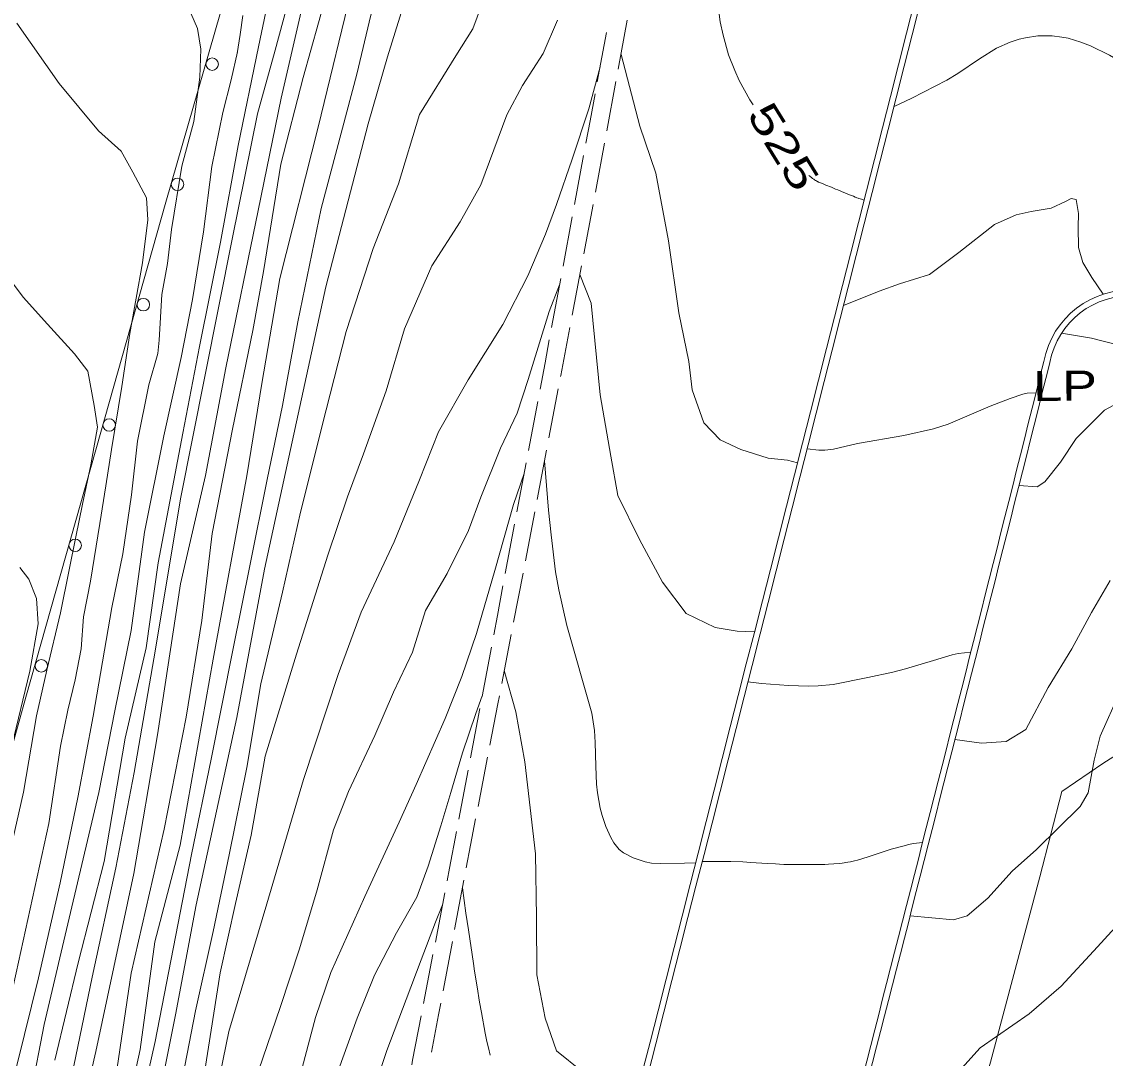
# Model space of a CAD drawing. Extents: x 2361284 to 2366480, y 6976556 to 6985346.
# Drawn here: x 2364861 to 2365034.3, y 6979380.2 to 6979546 of the extents above; entities that cross this region are included whole.
import ezdxf
from ezdxf.enums import TextEntityAlignment as Align

# ---------------------------------------------------------------- set-up
doc = ezdxf.new("R2010")
doc.units = 0
doc.header["$LTSCALE"] = 1.9
for name, color, linetype, lineweight in [('12', 7, 'Continuous', 13), ('13', 7, 'Continuous', 13), ('17', 7, 'Continuous', 13), ('3', 7, 'Continuous', 13), ('4', 7, 'Continuous', 13), ('6', 7, 'Continuous', 13)]:
    doc.layers.add(name, color=color, linetype=linetype, lineweight=lineweight)

msp = doc.modelspace()

# ---------------------------------------------------------------- linework, layer by layer
at = {"layer": '12'}
for points in [[(2364940.572, 6979651.492), (2364936.015, 6979640.658), (2364930.882, 6979627.349), (2364925.567, 6979614.168), (2364922.442, 6979603.148), (2364918.936, 6979587.914), (2364916.601, 6979576.84), (2364913.39, 6979563.3), (2364906.039, 6979537.048), (2364902.512, 6979523.173), (2364899.694, 6979506.046), (2364898.034, 6979496.58), (2364894.763, 6979480.837), (2364891.482, 6979464.115), (2364889.854, 6979450.23), (2364887.37, 6979434.784), (2364883.83, 6979416.87), (2364878.53, 6979393.849), (2364876.088, 6979377.264)], [(2364882.837, 6979492.905), (2364883.027, 6979495.067), (2364883.438, 6979502.371), (2364884.341, 6979507.3), (2364884.999, 6979512.745), (2364886.643, 6979522.873), (2364888.565, 6979530.031), (2364889.557, 6979537.121), (2364889.675, 6979541.602), (2364889.163, 6979544.897), (2364888.08, 6979547.307), (2364885.482, 6979551.383), (2364883.032, 6979555.57), (2364880.347, 6979560.225), (2364874.227, 6979570.787), (2364867.702, 6979580.676), (2364859.865, 6979594.061)], [(2364978.005, 6979532.672), (2364977.497, 6979533.487), (2364975.8, 6979536.569), (2364975.062, 6979538.169), (2364974.099, 6979540.655), (2364973.198, 6979543.811), (2364972.767, 6979545.938), (2364972.187, 6979550.237), (2364971.913, 6979555.136), (2364971.713, 6979561.675), (2364971.378, 6979564.921), (2364969.835, 6979573.586), (2364968.582, 6979579.184), (2364967.889, 6979581.263), (2364967.429, 6979582.294), (2364966.638, 6979583.721), (2364965.766, 6979584.888), (2364965.313, 6979585.334)], [(2364946.715, 6979546.205), (2364944.445, 6979540.863), (2364941.153, 6979535.761), (2364938.647, 6979531.077), (2364934.493, 6979519.867), (2364931.161, 6979513.945), (2364926.627, 6979506.932), (2364922.272, 6979496.88), (2364919.306, 6979486.94), (2364915.691, 6979476.877), (2364913.126, 6979470.022), (2364909.985, 6979460.681), (2364904.976, 6979444.852), (2364899.991, 6979428.514), (2364897.731, 6979415.882), (2364895.224, 6979404.968), (2364892.809, 6979393.874), (2364890.358, 6979378.279)], [(2365043.569, 6979537.876), (2365040.968, 6979538.031), (2365038.905, 6979538.365), (2365037.901, 6979538.691), (2365036.887, 6979539.274), (2365035.656, 6979540.226), (2365035.002, 6979540.644), (2365031.989, 6979542.103), (2365030.403, 6979542.72), (2365028.393, 6979543.31), (2365027.374, 6979543.516), (2365025.84, 6979543.707), (2365023.562, 6979543.705), (2365021.562, 6979543.414), (2365020.569, 6979543.173), (2365019.094, 6979542.694), (2365016.941, 6979541.712), (2365014.212, 6979540.026), (2365010.772, 6979537.666), (2365008.98, 6979536.597), (2365003.418, 6979533.731), (2365000.558, 6979532.436)], [(2364995.76, 6979517.45), (2364995.34, 6979517.581), (2364995.131, 6979517.648), (2364994.922, 6979517.717), (2364994.818, 6979517.753), (2364994.612, 6979517.827), (2364994.509, 6979517.866), (2364994.356, 6979517.926), (2364994.043, 6979518.053), (2364993.418, 6979518.309), (2364992.17, 6979518.824), (2364991.545, 6979519.08), (2364991.211, 6979519.216), (2364990.542, 6979519.487), (2364989.649, 6979519.847), (2364989.203, 6979520.027), (2364988.534, 6979520.301), (2364988.468, 6979520.329), (2364988.425, 6979520.349), (2364988.338, 6979520.39), (2364988.296, 6979520.411), (2364988.212, 6979520.455), (2364988.129, 6979520.502), (2364988.074, 6979520.534), (2364987.966, 6979520.601), (2364987.846, 6979520.679), (2364987.767, 6979520.733), (2364987.714, 6979520.77), (2364987.611, 6979520.845), (2364987.533, 6979520.902), (2364987.38, 6979521.019), (2364987.076, 6979521.257), (2364986.923, 6979521.376)], [(2364882.837, 6979492.905), (2364881.395, 6979487.89), (2364879.56, 6979478.913), (2364878.582, 6979470.324), (2364877.232, 6979460.909), (2364875.454, 6979452.323), (2364872.478, 6979434.953), (2364870.052, 6979421.929), (2364867.211, 6979408.282), (2364863.756, 6979393.098), (2364860.355, 6979379.514), (2364856.233, 6979363.845), (2364853.513, 6979348.078), (2364849.969, 6979332.753), (2364847.388, 6979320.178), (2364844.32, 6979304.148), (2364840.793, 6979286.013), (2364838.285, 6979270.979), (2364835.638, 6979258.063), (2364833.335, 6979244.72), (2364830.431, 6979230.282), (2364828.957, 6979222.287)], [(2365090.866, 6979426.919), (2365090.797, 6979426.888), (2365083.489, 6979425.51), (2365077.442, 6979424.101), (2365067.089, 6979423.363), (2365058.669, 6979422.293), (2365053.493, 6979419.673), (2365048.99, 6979416.8), (2365044.078, 6979409.723), (2365038.145, 6979403.617), (2365033.068, 6979398.048), (2365027.257, 6979391.763), (2365022.139, 6979387.334), (2365014.301, 6979381.889), (2365009.957, 6979377.046), (2365004.624, 6979368.746), (2365002.393, 6979364.705), (2364999.96, 6979360.762), (2364997.599, 6979357.698), (2364995.39, 6979356.567), (2364991.199, 6979356.597)], [(2364935.966, 6979380.723), (2364935.687, 6979381.895), (2364935.427, 6979382.932), (2364935.305, 6979383.451), (2364935.143, 6979384.236), (2364934.553, 6979387.531), (2364934.269, 6979389.181), (2364933.858, 6979391.658), (2364933.466, 6979394.138), (2364933.278, 6979395.379), (2364932.481, 6979400.747), (2364932.091, 6979403.432), (2364931.533, 6979407.463)], [(2364928.338, 6979404.773), (2364927.195, 6979401.991), (2364924.932, 6979395.96), (2364922.532, 6979389.637), (2364919.419, 6979381.457), (2364916.6, 6979372.929), (2364914.535, 6979364.97), (2364911.915, 6979356.603), (2364906.81, 6979342.444), (2364903.391, 6979331.771), (2364900.674, 6979323.105), (2364897.677, 6979314.345), (2364893.693, 6979298.897), (2364889.623, 6979284.088), (2364887.079, 6979275.043), (2364882.952, 6979258.982), (2364879.363, 6979246.318), (2364877.403, 6979235.749), (2364874.144, 6979219.817), (2364873.874, 6979218.664)]]:
    msp.add_lwpolyline(points, dxfattribs=at)
at = {"layer": '13'}
for points in [[(2364935.333, 6979655.622), (2364928.819, 6979637.17), (2364924.211, 6979622.164), (2364920.914, 6979610.323), (2364917.173, 6979595.526), (2364914.152, 6979585.168), (2364910.099, 6979567.598), (2364905.595, 6979546.914), (2364902.541, 6979533.764), (2364898.872, 6979515.768), (2364893.72, 6979490.627), (2364890.423, 6979473.406), (2364886.458, 6979456.087), (2364882.777, 6979431.951), (2364879.008, 6979409.764), (2364875.761, 6979394.812), (2364872.908, 6979381.345), (2364870.69, 6979371.582)], [(2364972.406, 6979649.256), (2364970.163, 6979644.333), (2364968.074, 6979639.953), (2364963.921, 6979634.903), (2364960.591, 6979630.721), (2364957.961, 6979623.415), (2364954.16, 6979617.23), (2364948.611, 6979611.777), (2364942.665, 6979607.17), (2364938.23, 6979601.287), (2364934.841, 6979592.725), (2364931.963, 6979582.107), (2364926.884, 6979565.097), (2364922.751, 6979550.677), (2364919.548, 6979540.336), (2364916.469, 6979529.666), (2364909.707, 6979503.571), (2364899.857, 6979458.424), (2364895.431, 6979434.731), (2364888.966, 6979404.758), (2364885.633, 6979387.166), (2364879.447, 6979356.225)], [(2364944.843, 6979646.232), (2364936.571, 6979628.433), (2364929.501, 6979610.655), (2364925.161, 6979595.902), (2364921.328, 6979581.526), (2364916.735, 6979563.751), (2364914.171, 6979552.636), (2364908.455, 6979529.09), (2364902.325, 6979504.911), (2364899.465, 6979488.122), (2364897.074, 6979473.349), (2364891.643, 6979444.025), (2364886.415, 6979414.294), (2364882.332, 6979398.854), (2364880.005, 6979381.662), (2364874.888, 6979358.181)], [(2364956.006, 6979647.11), (2364951.471, 6979642.325), (2364947.492, 6979637.947), (2364941.272, 6979628.438), (2364937.061, 6979616.947), (2364931.292, 6979600.081), (2364928.01, 6979588.64), (2364924.91, 6979577.069), (2364922.999, 6979567.72), (2364920.43, 6979559.186), (2364918.737, 6979553.119), (2364916.884, 6979547.031), (2364914.644, 6979537.559), (2364908.918, 6979516.094), (2364905.231, 6979497.958), (2364902.738, 6979484.593), (2364900.311, 6979472.75), (2364897.559, 6979459.242), (2364894.829, 6979445.486), (2364891.364, 6979428.052), (2364888.219, 6979412.812), (2364882.393, 6979382.925), (2364876.991, 6979358.992)], [(2364924.07, 6979630.764), (2364923.104, 6979628.225), (2364920.936, 6979621.683), (2364917.506, 6979609.921), (2364914.233, 6979597.678), (2364910.081, 6979577.908), (2364905.769, 6979557.026), (2364901.568, 6979541.425), (2364898.735, 6979531.228), (2364894.751, 6979511.488), (2364890.333, 6979489.235), (2364886.428, 6979469.678), (2364882.457, 6979445.638), (2364879.054, 6979425.925), (2364876.08, 6979410.666), (2364872.305, 6979393.189), (2364867.085, 6979367.959)], [(2364909.62, 6979588.435), (2364908.556, 6979584.645), (2364906.306, 6979575.252), (2364902.453, 6979558.775), (2364898.923, 6979541.95), (2364895.682, 6979526.189), (2364892.859, 6979510.71), (2364889.457, 6979494.058), (2364886.829, 6979480.162), (2364882.866, 6979459.453), (2364880.965, 6979445.874), (2364877.593, 6979431.441), (2364874.219, 6979411.718), (2364870.103, 6979395.469), (2364866.361, 6979379.951)], [(2364937.525, 6979556.518), (2364933.176, 6979544.826), (2364930.458, 6979540.5), (2364924.677, 6979531.135), (2364921.292, 6979520.052), (2364917.249, 6979509.722), (2364912.915, 6979496.421), (2364909.734, 6979483.889), (2364905.63, 6979467.57), (2364902.762, 6979454.762), (2364899.311, 6979440.088), (2364897.077, 6979426.726), (2364894.25, 6979412.769), (2364891.687, 6979400.483), (2364888.857, 6979387.816), (2364886.14, 6979373.829)], [(2364869.603, 6979440.726), (2364870.566, 6979445.705), (2364870.937, 6979450.8), (2364872.043, 6979456.5), (2364873.565, 6979465.755), (2364874.478, 6979471.775), (2364875.434, 6979477.564), (2364877.088, 6979487.619), (2364878.327, 6979496.122), (2364880.36, 6979507.402), (2364881.224, 6979514.311), (2364881.031, 6979517.799), (2364878.802, 6979521.908), (2364876.931, 6979525.26), (2364873.308, 6979528.526), (2364867.066, 6979536.108), (2364860.284, 6979545.743)], [(2364895.492, 6979540.907), (2364896.003, 6979543.942), (2364896.434, 6979546.977)], [(2364895.539, 6979541.138), (2364894.552, 6979536.669), (2364893.232, 6979531.436), (2364891.473, 6979522.828), (2364890.133, 6979512.354), (2364888.386, 6979501.538), (2364886.534, 6979492.27), (2364883.793, 6979479.753), (2364880.669, 6979464.362), (2364878.578, 6979448.652), (2364875.951, 6979435.806), (2364873.404, 6979422.751), (2364869.058, 6979404.469), (2364864.647, 6979385.616), (2364862.559, 6979374.855)], [(2364985.099, 6979475.456), (2364983.535, 6979475.882), (2364980.392, 6979476.202), (2364976.029, 6979477.55), (2364972.734, 6979479.119), (2364970.108, 6979481.823), (2364968.278, 6979487.086), (2364967.724, 6979491.661), (2364966.12, 6979499.407), (2364964.481, 6979510.951), (2364962.457, 6979521.743), (2364959.876, 6979529.279), (2364956.887, 6979540.741)], [(2364953.546, 6979538.739), (2364951.73, 6979532.022), (2364949.096, 6979523.986), (2364946.595, 6979516.742), (2364944.83, 6979511.974), (2364942.013, 6979505.338), (2364937.966, 6979497.559), (2364932.421, 6979488.705), (2364927.679, 6979480.421), (2364924.672, 6979472.712), (2364920.626, 6979462.822), (2364915.322, 6979451.562), (2364911.657, 6979441.586), (2364906.137, 6979424.832), (2364900.236, 6979404.905), (2364894.169, 6979384.497), (2364889.513, 6979361.892), (2364883.686, 6979331.134), (2364880.421, 6979314.802), (2364874.826, 6979288.987), (2364868.833, 6979255.629), (2364866.279, 6979245.533), (2364861.641, 6979217.898), (2364861.05, 6979214.832)], [(2365033.966, 6979502.402), (2365032.191, 6979505.046), (2365030.748, 6979507.462), (2365030.034, 6979509.865), (2365029.973, 6979513.094), (2365030.042, 6979515.296), (2365029.681, 6979517.552), (2365028.889, 6979517.695), (2365027.974, 6979517.206), (2365025.674, 6979516.134), (2365022.459, 6979515.634), (2365020.074, 6979515.101), (2365016.609, 6979513.547), (2365010.912, 6979509.043), (2365006.224, 6979505.539), (2365001.428, 6979504.043), (2364998.159, 6979502.902), (2364992.48, 6979500.598)], [(2364859.203, 6979413.346), (2364861.363, 6979422.797), (2364863.427, 6979434.987), (2364865.058, 6979442.273), (2364867.251, 6979451.465), (2364868.645, 6979458.357), (2364869.726, 6979463.598), (2364870.766, 6979468.848), (2364872.096, 6979475.142), (2364873.189, 6979481.142), (2364872.616, 6979484.596), (2364871.624, 6979490.107), (2364869.487, 6979492.848), (2364865.172, 6979497.607), (2364861.301, 6979501.941), (2364853.552, 6979512.236)], [(2365136.183, 6979508.484), (2365136.586, 6979507.058), (2365136.033, 6979504.213), (2365135.218, 6979500.525), (2365133.793, 6979497.911), (2365131.011, 6979497.055), (2365124.137, 6979495.429), (2365116.349, 6979494.055), (2365107.943, 6979491.484), (2365098.369, 6979488.793), (2365081.731, 6979486.335), (2365065.689, 6979485.362), (2365045.006, 6979486.656), (2365037.078, 6979485.43), (2365034.204, 6979483.851), (2365029.694, 6979479.341), (2365027.14, 6979475.546), (2365024.67, 6979472.403), (2365023.426, 6979471.618), (2365020.525, 6979471.793)], [(2364978.226, 6979448.4), (2364975.474, 6979448.544), (2364971.939, 6979449.13), (2364967.317, 6979451.356), (2364963.509, 6979456.359), (2364959.855, 6979463.175), (2364956.387, 6979470.223), (2364955.248, 6979476.513), (2364953.535, 6979486.296), (2364952.105, 6979500.984), (2364950.311, 6979505.537)], [(2364947.057, 6979503.896), (2364945.387, 6979499.63), (2364943.661, 6979493.943), (2364942.021, 6979488.766), (2364940.29, 6979483.4), (2364937.604, 6979477.785), (2364934.478, 6979469.935), (2364932.489, 6979464.645), (2364929.105, 6979457.722), (2364925.641, 6979451.83), (2364923.544, 6979445.159), (2364920.515, 6979438.78), (2364917.529, 6979431.861), (2364913.295, 6979422.87), (2364910.893, 6979416.767), (2364908.294, 6979407.182), (2364905.484, 6979397.744), (2364902.442, 6979388.496), (2364898.909, 6979378.251)], [(2365080.978, 6979497.149), (2365080.476, 6979495.604), (2365080.07, 6979494.86), (2365079.172, 6979493.838), (2365078.451, 6979493.323), (2365077.929, 6979493.054), (2365076.81, 6979492.699), (2365074.425, 6979492.327), (2365073.23, 6979492.224), (2365071.438, 6979492.176), (2365068.763, 6979492.353), (2365062.355, 6979493.172), (2365056.73, 6979493.923), (2365053.905, 6979494.142), (2365051.202, 6979494.17), (2365045.795, 6979494.064), (2365038.767, 6979493.948), (2365038.014, 6979493.995), (2365036.527, 6979494.244), (2365033.583, 6979495.021), (2365032.103, 6979495.354), (2365027.334, 6979496.179)], [(2365023.254, 6979486.649), (2365021.847, 6979486.575), (2365021.146, 6979486.429), (2365019.113, 6979485.749), (2365015.916, 6979484.479), (2365009.193, 6979481.606), (2365006.876, 6979480.848), (2365002.119, 6979479.788), (2364994.69, 6979478.518), (2364990.849, 6979477.631), (2364989.458, 6979477.484), (2364988.52, 6979477.485), (2364986.649, 6979477.651)], [(2364968.836, 6979411.498), (2364967.027, 6979411.451), (2364963.236, 6979411.355), (2364961.75, 6979411.455), (2364960.772, 6979411.654), (2364958.828, 6979412.283), (2364957.269, 6979413.091), (2364956.596, 6979413.639), (2364955.745, 6979414.684), (2364955.245, 6979415.542), (2364954.445, 6979417.277), (2364953.865, 6979419.04), (2364953.575, 6979420.234), (2364953.149, 6979422.669), (2364952.989, 6979424.083), (2364952.855, 6979426.933), (2364952.778, 6979430.736), (2364952.658, 6979432.622), (2364952.218, 6979435.411), (2364948.245, 6979449.425), (2364946.928, 6979455.145), (2364946.433, 6979458.037), (2364945.714, 6979463.926), (2364945.311, 6979467.857), (2364944.655, 6979475.732)], [(2364941.392, 6979473.751), (2364939.69, 6979468.753), (2364936.73, 6979458.235), (2364933.786, 6979448.147), (2364931.451, 6979441.294), (2364928.775, 6979434.538), (2364924.136, 6979423.994), (2364921.402, 6979417.997), (2364915.934, 6979406.095), (2364910.509, 6979393.973), (2364908.008, 6979386.729), (2364903.974, 6979371.438)], [(2364859.435, 6979429.989), (2364862.349, 6979442.127), (2364863.677, 6979449.701), (2364863.399, 6979453.747), (2364862.17, 6979456.826), (2364860.742, 6979458.692)], [(2365035.091, 6979456.62), (2365032.12, 6979451.492), (2365028.974, 6979445.691), (2365025.182, 6979439.535), (2365021.636, 6979432.801), (2365018.485, 6979430.861), (2365014.548, 6979430.623), (2365010.282, 6979431.183)], [(2365012.829, 6979445.158), (2365010.823, 6979444.945), (2365009.843, 6979444.719), (2365006.871, 6979443.821), (2365002.373, 6979442.478), (2365000.378, 6979441.976), (2364996.346, 6979441.141), (2364990.796, 6979440.018), (2364988.429, 6979439.757), (2364986.842, 6979439.722), (2364983.668, 6979439.82), (2364979.348, 6979440.144), (2364977.192, 6979440.429)], [(2364960.006, 6979376.831), (2364957.759, 6979376.44), (2364954.094, 6979376.955), (2364950.663, 6979378.123), (2364946.581, 6979381.425), (2364944.782, 6979386.648), (2364943.416, 6979393.555), (2364943.388, 6979402.775), (2364943.212, 6979412.914), (2364941.511, 6979427.649), (2364940.075, 6979435.606), (2364938.222, 6979442.218)], [(2364869.603, 6979440.726), (2364868.429, 6979435.874), (2364867.243, 6979430.163), (2364865.381, 6979417.765), (2364860.178, 6979393.884), (2364855.794, 6979374.291), (2364851.902, 6979355.493), (2364849.143, 6979341.746), (2364845.432, 6979322.93), (2364841.802, 6979303.984), (2364837.25, 6979281.06), (2364834.028, 6979264.388), (2364832.067, 6979252.869), (2364829.179, 6979236.83), (2364826.929, 6979225.208), (2364826.786, 6979224.487)], [(2364934.67, 6979438.164), (2364933.658, 6979435.365), (2364931.528, 6979429.064), (2364929.678, 6979422.716), (2364928.068, 6979417.421), (2364926.03, 6979410.951), (2364924.247, 6979406.004), (2364920.991, 6979400.312), (2364917.444, 6979393.539), (2364914.689, 6979386.632), (2364911.698, 6979378.382)], [(2365036.668, 6979438.747), (2365033.508, 6979431.714), (2365032.562, 6979427.876), (2365031.585, 6979422.702), (2365030.324, 6979420.503), (2365023.309, 6979413.596), (2365019.462, 6979410.129), (2365015.553, 6979405.842), (2365012.24, 6979402.999), (2365010.036, 6979402.368), (2365003.118, 6979403.023)], [(2365005.107, 6979414.743), (2365004.125, 6979414.633), (2365003.637, 6979414.56), (2365003.152, 6979414.467), (2365002.91, 6979414.412), (2365001.963, 6979414.171), (2365000.087, 6979413.645), (2364999.435, 6979413.45), (2364998.143, 6979413.031), (2364996.424, 6979412.456), (2364995.557, 6979412.181), (2364994.679, 6979411.926), (2364994.235, 6979411.809), (2364993.582, 6979411.659), (2364993.144, 6979411.575), (2364992.267, 6979411.441), (2364991.827, 6979411.389), (2364990.945, 6979411.31), (2364990.061, 6979411.259), (2364989.471, 6979411.238), (2364988.291, 6979411.213), (2364986.495, 6979411.195), (2364985.596, 6979411.194), (2364984.249, 6979411.206), (2364982.902, 6979411.239), (2364982.229, 6979411.265), (2364981.577, 6979411.298), (2364980.275, 6979411.38), (2364977.67, 6979411.558), (2364976.366, 6979411.62), (2364974.443, 6979411.672), (2364973.481, 6979411.687), (2364972.039, 6979411.696), (2364969.875, 6979411.678)]]:
    msp.add_lwpolyline(points, dxfattribs=at)
at = {"layer": '17'}
msp.add_lwpolyline([(2364960.332, 6979715.804), (2364953.874, 6979703.002), (2364947.566, 6979690.12), (2364938.457, 6979670.954), (2364929.782, 6979651.579), (2364922.227, 6979633.087), (2364915.114, 6979614.418), (2364908.287, 6979596.122), (2364901.984, 6979577.641), (2364892.839, 6979547.433), (2364884.097, 6979517.108), (2364872.883, 6979477.54), (2364861.719, 6979437.951), (2364849.426, 6979394.022), (2364837.123, 6979350.092), (2364827.923, 6979317.333), (2364818.705, 6979284.573), (2364810.926, 6979257.128), (2364802.845, 6979229.78), (2364801.116, 6979224.323), (2364799.328, 6979218.886), (2364798.239, 6979215.595), (2364797.15, 6979212.315)], dxfattribs=at)
for centre in [(2364891.504, 6979539.179), (2364885.962, 6979519.962), (2364880.494, 6979500.729), (2364875.039, 6979481.487), (2364869.606, 6979462.24), (2364864.179, 6979442.99)]:
    msp.add_circle(centre, 1, dxfattribs=at)
at = {"layer": '3'}
for p, q in [((2365024.507, 6979491.652), (2365024.507, 6979491.651)), ((2365025.451, 6979491.473), (2365025.439, 6979491.419))]:
    msp.add_line(p, q, dxfattribs=at)
for points in [[(2365027.381, 6979422.865), (2365033.957, 6979427.349), (2365037.3, 6979429.496), (2365042.451, 6979432.489), (2365054.047, 6979438.654), (2365077.349, 6979450.752), (2365124.324, 6979474.72), (2365150.592, 6979487.69), (2365155.633, 6979490.467), (2365162.234, 6979494.395), (2365165.591, 6979496.264), (2365168.435, 6979497.7), (2365174.243, 6979500.326)], [(2365050.009, 6979199.098), (2365032.43, 6979236.923), (2365008.922, 6979281.862), (2365005.349, 6979287.301), (2365000.59, 6979294.527), (2364999.182, 6979298.53), (2364998.395, 6979304.453), (2364997.796, 6979308.648), (2364998.235, 6979313.971), (2365000.264, 6979321.472), (2365004.358, 6979335.761), (2365010.528, 6979360.042), (2365015.963, 6979379.624), (2365023.85, 6979409.241), (2365027.391, 6979422.905)]]:
    msp.add_lwpolyline(points, dxfattribs=at)
for centre, radius, start, end in [((2254491.927, 7007547.162), 114003.346, 345.63172, 345.79902), ((2254491.927, 7007547.162), 114004.305, 345.63172, 345.79902), ((2365038.33, 6979489.03), 14.069, 85.92585, 169.25954), ((2365038.33, 6979489.03), 13.109, 85.92585, 169.25954), ((2347412.153, 6983892.202), 18153.784, 345.45358, 345.97153), ((2347412.154, 6983892.202), 18154.743, 345.45358, 345.97153)]:
    msp.add_arc(centre, radius, start, end, dxfattribs=at)
at = {"layer": '6'}
for p, q in [((2364957.855, 6979546.241), (2364956.42, 6979538.367)), ((2364953.098, 6979536.376), (2364954.564, 6979544.239)), ((2364956.058, 6979536.404), (2364954.623, 6979528.529)), ((2364949.445, 6979516.719), (2364950.91, 6979524.584)), ((2364952.445, 6979516.738), (2364950.96, 6979508.873)), ((2364947.618, 6979506.892), (2364949.084, 6979514.756)), ((2364950.588, 6979506.91), (2364949.093, 6979499.055)), ((2364945.782, 6979497.064), (2364947.247, 6979504.928)), ((2364946.855, 6979487.262), (2364945.36, 6979479.409)), ((2364942.099, 6979477.408), (2364943.574, 6979485.271)), ((2364944.988, 6979477.445), (2364943.493, 6979469.591)), ((2364940.241, 6979467.579), (2364941.726, 6979475.444)), ((2364943.122, 6979467.626), (2364941.615, 6979459.771)), ((2364938.384, 6979457.751), (2364939.87, 6979465.615)), ((2364941.234, 6979457.808), (2364939.718, 6979449.954)), ((2364939.337, 6979447.99), (2364937.812, 6979440.134)), ((2364934.661, 6979438.104), (2364936.156, 6979445.959)), ((2364932.805, 6979428.276), (2364934.29, 6979436.141)), ((2364935.534, 6979428.352), (2364934.019, 6979420.497)), ((2364930.949, 6979418.448), (2364932.434, 6979426.313)), ((2364931.771, 6979408.715), (2364930.286, 6979400.85)), ((2364927.195, 6979398.81), (2364928.71, 6979406.666)), ((2364929.915, 6979398.886), (2364928.439, 6979391.023)), ((2364925.308, 6979388.993), (2364926.814, 6979396.848))]:
    msp.add_line(p, q, dxfattribs=at)
for points in [[(2364951.282, 6979526.547), (2364951.938, 6979530.094), (2364952.737, 6979534.411)], [(2364954.262, 6979526.566), (2364952.931, 6979519.303), (2364952.816, 6979518.701)], [(2364948.722, 6979497.092), (2364947.265, 6979489.406), (2364947.226, 6979489.226)], [(2364943.945, 6979487.235), (2364944.735, 6979491.422), (2364945.42, 6979495.1)], [(2364936.528, 6979447.923), (2364937.118, 6979451.039), (2364938.013, 6979455.787)], [(2364937.43, 6979438.171), (2364937.192, 6979436.918), (2364935.915, 6979430.316)], [(2364933.638, 6979418.534), (2364932.828, 6979414.316), (2364932.142, 6979410.679)], [(2364929.082, 6979408.63), (2364929.473, 6979410.654), (2364930.577, 6979416.484)], [(2364928.068, 6979389.059), (2364927.706, 6979387.156), (2364926.583, 6979381.195)], [(2364923.422, 6979379.174), (2364923.564, 6979379.935), (2364924.927, 6979387.029)]]:
    msp.add_lwpolyline(points, dxfattribs=at)

# ---------------------------------------------------------------- texts
at = {"layer": '12', "width": 1.4}
msp.add_text(' 525 ', height=4.799, rotation=301.754, dxfattribs=at).set_placement((2364980.841, 6979524.752), align=Align.CENTER)
at = {"layer": '4', "width": 1.3}
msp.add_text('  LP', height=4.799, rotation=0.545, dxfattribs=at).set_placement((2365018.177, 6979485.27))

doc.saveas('drawing.dxf')
